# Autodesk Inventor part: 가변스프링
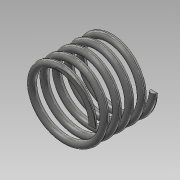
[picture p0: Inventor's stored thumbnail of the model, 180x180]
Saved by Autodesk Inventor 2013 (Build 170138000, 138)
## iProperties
Created: 2019-01
Part Number: 가변스프링
Material: 스테인리스강
Document SubType Name: Modeling
Designer: Administrator
Density: 7.15 g/cm^3
Mass: 6.91448 g
Surface Area: 19.6267 cm^2
Volume: 0.967061 cm^3
Author: Administrator
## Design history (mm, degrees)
sketch "스케치1"
  geometry: L1 (0, 0)-(10, 0); L2 (10, 0)-(10, 18.7); L3 (10, 18.7)-(0, 18.7); L4 (0, 18.7)-(0, 0); C1 r 1 at (10, 0)
  constraints: 8 end point, 2 parallel, 1 centre point, 1 coincident, 1 horizontal, 1 perpendicular
  dimensions: "d0" = 18.7 distance of L3.end L1.start (derived); "d1" = 2 diameter of C1; "d2" = 20 diameter of L2 L4
feature "코일1" pitch "d3" = 10; turns "d5" = 5; dims "d4" = 18.7 (= d0), "d6" = 0, angle "d7" = 90 deg, angle "d8" = 90 deg, "d9" = 0, "d10" = 0
sketch "스케치2"
  geometry: L1 (-9, 0)-(-11, 0) reference; 1 further point
  constraints: 1 horizontal alignment
extrude "돌출1" cut sketch "스케치2" stored distance "d11" = 10; taper "d12" = 0 deg
node "작업 평면1"
sketch "스케치3"
  geometry: L1 (-1, 0)-(1, 0) reference; 1 further point
  constraints: 1 horizontal alignment
extrude "돌출2" cut sketch "스케치3" stored distance "d14" = 10; taper "d15" = 0 deg
node "솔리드1"
node "절단 모서리 투영1"
node "절단 모서리 투영2"
other parameters: "d13" = 90 deg
